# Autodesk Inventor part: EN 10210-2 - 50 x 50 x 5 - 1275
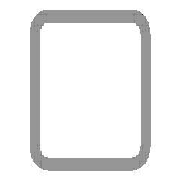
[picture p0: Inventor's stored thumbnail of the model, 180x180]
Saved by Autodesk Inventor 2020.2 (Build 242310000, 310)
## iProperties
IsCustomPart: 1
_CCFamilyMember: 16
_CCFamilyDisplayName: DIN EN 10210-2 (USAS B17.1 quadratisch) - Rohrleitung — In Klammern angegebene Größen wurden aufgehoben
_FrameMemberDoc: Frame Member File
_Version: 15.0.0
_GetPNFromCC: 1
Created: 2019-10
Part Number: EN 10210-2 - 50 x 50 x 5 - 1275
Material: Stahl, weich
Description: Rohrleitung
Document SubType Name: Modeling
Standard: DIN
Designer: lutzd
Standard Revision: 2006-07
Standards Organization: DIN
Language: de-DE
Size Designation: 50 x 50 x 5
Categories: <MemberInstance><Categories><Category DisplayName="Profile" InternalName="089c4875-fa83-4c05-b084-43b9cc11f5ed" Mnemonic="GRDR"><CategoryParameter DisplayName="
Stock Number: 50 x 50 x 5
Mass: 8739.39 g
Surface Area: 4333.85 cm^2
Volume: 1113.3 cm^3
Density: 7.85 g/cm^3
Appearance: Semi-Polished(8)
G_L: 1275,000 mm
G_W: 50,000 mm
G_H: 50,000 mm
Dimensions: 50x50x1275 mm
Mass: 8,739 kg
DocNumber: ADSK-014286
Folder: .
+458FB16A-BDB5-4860-B6EA-2D9B138E7D68+SCHNITTDETAIL1: Schnittwinkel 90,00 grd
VLT_Material: Stahl, weich
+0595C7C7-D9C4-48CC-868B-FFD1E552B11A+SCHNITTDETAIL2: Schnittwinkel 90,00 grd
Title: Profil-Bauteil
Author: lutzd
Revision Number: -
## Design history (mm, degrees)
node "Startebene"
node "Endebene"
sketch "Skizze"
  geometry: L1 (-25, -17.5)-(-25, 17.5); L2 (-17.5, 25)-(17.5, 25); L3 (25, 17.5)-(25, -17.5); L4 (17.5, -25)-(-17.5, -25); L5 (-15, 20)-(15, 20); L6 (20, 15)-(20, -15); L7 (15, -20)-(-15, -20); L8 (-20, -15)-(-20, 15); L9 (0, 37.175)-(0, -37.175) reference; L10 (-37.175, 0)-(37.175, 0) reference; A1 r 7.5 centre (-17.5, -17.5) between (-25, -17.5) and (-17.5, -25); A2 r 7.5 centre (-17.5, 17.5) between (-17.5, 25) and (-25, 17.5); A3 r 7.5 centre (17.5, 17.5) between (25, 17.5) and (17.5, 25); A4 r 7.5 centre (17.5, -17.5) between (17.5, -25) and (25, -17.5); A5 r 5 centre (-15, -15) between (-20, -15) and (-15, -20); A6 r 5 centre (-15, 15) between (-15, 20) and (-20, 15); A7 r 5 centre (15, 15) between (20, 15) and (15, 20); A8 r 5 centre (15, -15) between (15, -20) and (20, -15)
  constraints: 16 end point, 16 point on circle, 16 tangent, 8 centre point, 6 equal radius, 4 parallel, 2 perpendicular, 2 other
  dimensions: "d7" = 7.5 radius of A1 (= G_IR); "d10" = 50 distance between parallel lines of L2 L4 (= G_H); "d11" = 50 distance between parallel lines of L1 L3 (= G_W); "d12" = 5 distance between parallel lines of L3 L6 (= G_T); "d15" = 25 distance between parallel lines of L2 L10 (= 0.5 x d10); "d16" = 25 distance between parallel lines of L9 L3 (= 0.5 x d11); "d19" = 5 radius of A5 (= G_T); "d20" = 5 distance between parallel lines of L4 L7 (= G_T)
extrude "Körper" new body sketch "Skizze" stored distance "d3" = 1275 (= G_L); taper "d4" = 0 deg
node "Driven Length"
  sketch "Sketch3"
    geometry: L1 (0, 0)-(10, 0) reference
    constraints: 2 end point, 1 horizontal
  workplane "Work Plane3"
  sketch "Sketch4"
    geometry: L1 (-2, 50)-(12, 50) reference; L2 (-2, 1325)-(12, 1325) reference
    dimensions: "d18" = 1275 distance between parallel lines of L1 L2 (derived)
workplane "Arbeitsebene4"
feature "Trennen1"
workplane "Arbeitsebene5"
feature "Trennen2"
body "Solid1"
other parameters: "G_W" = 50 [user parameter; used in 1 equation term], "G_H" = 50 [user parameter; used in 1 equation term], "G_T" = 5 [user parameter; used in 3 equation terms], "G_IR" = 7.5 [user parameter; used in 1 equation term], "G_L" = 1275 (= d18) [user parameter; used in 1 equation term], "d14" = 1325 (= G_OFFSET_END + B_L), "B_L" = 1375 [user parameter; used in 1 equation term], "d17" = 90 deg
